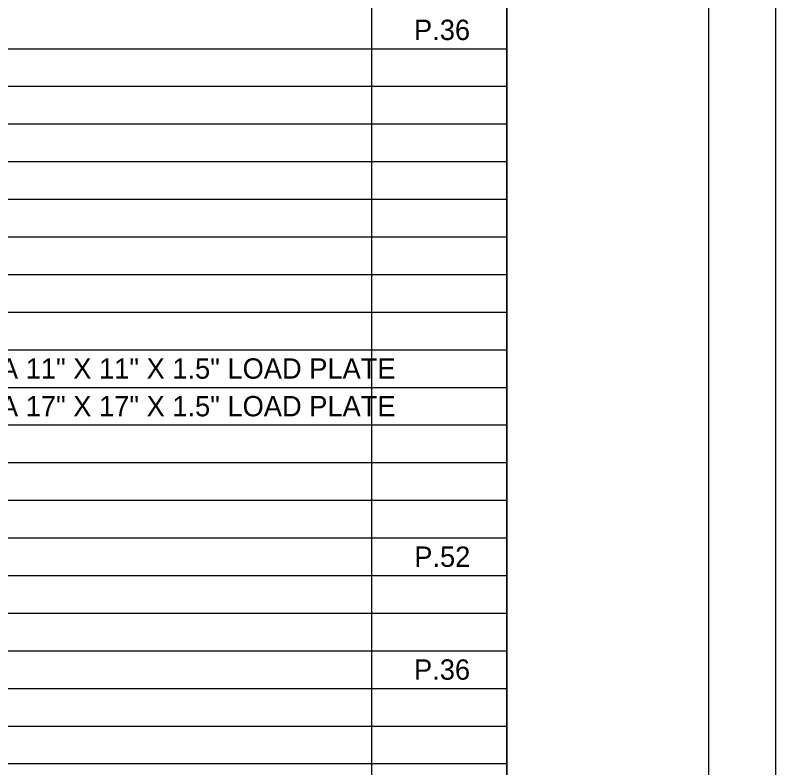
# Model space of a CAD drawing. Extents: x 0 to 34, y 0 to 22.
# Drawn here: x 28.35 to 34, y 5.51 to 11.11 of the extents above; entities that cross this region are included whole.
import ezdxf

# ---------------------------------------------------------------- set-up
doc = ezdxf.new("R2010")
doc.units = 0
for name, color, linetype in [('Default', 7, 'Continuous'), ('SH_Border', 7, 'Continuous'), ('SH_Cut_Line', 7, 'Continuous')]:
    doc.layers.add(name, color=color, linetype=linetype)

msp = doc.modelspace()

# ---------------------------------------------------------------- linework, layer by layer
at = {"layer": 'Default'}
for p, q in [((30.9954, 21.5), (30.9954, 0.5024)), ((32, 21.5), (32, 0.5024)), ((1.5, 10.8612), (32, 10.8612)), ((1.5, 10.5813), (32, 10.5813)), ((1.5, 10.3013), (32, 10.3013)), ((1.5, 10.0213), (32, 10.0213)), ((1.5, 9.7414), (32, 9.7414)), ((1.5, 9.4614), (32, 9.4614)), ((1.5, 9.1814), (32, 9.1814)), ((1.5, 8.9015), (32, 8.9015)), ((1.5, 8.6215), (32, 8.6215)), ((1.5, 8.3415), (32, 8.3415)), ((1.5, 8.0616), (32, 8.0616)), ((1.5, 7.7816), (32, 7.7816)), ((1.5, 7.5016), (32, 7.5016)), ((1.5, 7.2217), (32, 7.2217)), ((1.5, 6.9417), (32, 6.9417)), ((1.5, 6.6617), (32, 6.6617)), ((1.5, 6.3817), (32, 6.3817)), ((1.5, 6.1018), (32, 6.1018)), ((1.5, 5.8218), (32, 5.8218)), ((1.5, 5.5418), (32, 5.5418))]:
    msp.add_line(p, q, dxfattribs=at)
at = {"layer": 'SH_Border'}
msp.add_line((32, 0.5), (32, 21.5), dxfattribs=at)
msp.add_lwpolyline([(1.5, 21.5), (33.5, 21.5), (33.5, 0.5), (1.5, 0.5)], close=True, dxfattribs=at)
at = {"layer": 'SH_Cut_Line'}
msp.add_lwpolyline([(0, 0), (34, 0), (34, 22), (0, 22)], close=True, dxfattribs=at)

# ---------------------------------------------------------------- texts
at = {"layer": 'Default'}
for s, height, p in [('P.36', 0.15151, (31.3104, 10.9255)), ('ELASTOMERIC BEARING WITH INTERNAL LAMINATES AND LOAD PLATE (NEOPRENE)10" X 10" X 3.128" WITH A 11" X 11" X 1.5" LOAD PLATE', 0.1515119, (17.557, 8.4058)), ('ELASTOMERIC BEARING WITH INTERNAL LAMINATES AND LOAD PLATE (NEOPRENE)16" X 16" X 3.878" WITH A 17" X 17" X 1.5" LOAD PLATE', 0.1515119, (17.557, 8.1258)), ('P.52', 0.15151, (31.3122, 7.0059)), ('P.36', 0.15151, (31.3104, 6.166))]:
    msp.add_text(s, height=height, dxfattribs=at).set_placement(p)

doc.saveas('drawing.dxf')
